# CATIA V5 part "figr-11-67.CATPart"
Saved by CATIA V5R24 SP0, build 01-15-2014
Part number: Part2
Bounding box of the stored display mesh (mm): x -69 to 69, y -70.588 to 84.546, z -60.219 to 83.037
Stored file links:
  D:\KAVITA\CATIA V5-6R2014 Project_ Kavita\CATIA V5-6R2014_partfiles\Partfiles\c11_catia_v5-6r2014_prt\figr-11-67.CATPart
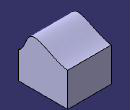
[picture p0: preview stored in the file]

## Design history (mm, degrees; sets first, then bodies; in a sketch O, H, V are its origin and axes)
Set1
  Extrude1: Element1 Sketch2, Lim1 134, Lim2 101, Direction yz-plane
Body1 (main body)
  Sketch1 on yz-plane, origin (0, 0, 0), H (0, 1, 0), V (0, 0, 1)
    line L1 (-70.5879, 56.2311) -> (84.546, 56.2311)
    line L2 (84.546, 56.2311) -> (84.546, -60.2191)
    line L3 (84.546, -60.2191) -> (-70.5879, -60.2191)
    line L4 (-70.5879, -60.2191) -> (-70.5879, 56.2311)
    horizontal: L1 H, L3 H
    vertical: L2 V, L4 V
  Pad1: profile Sketch1, direction (1, 0, 0), length 69, mirrored extent
  SewSurface1: SewingRemoveFace face of Pad1, SplitPlane Extrude1
  Sketch2 on yz-plane, origin (0, 0, 0), H (0, 1, 0), V (0, 0, 1)
    spline S1 through (-101.2957, 16.3509) (-51.8443, 49.0526) (-38.418, 74.5863) (34.1283, 62.9515) (100.0993, 49.0526)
